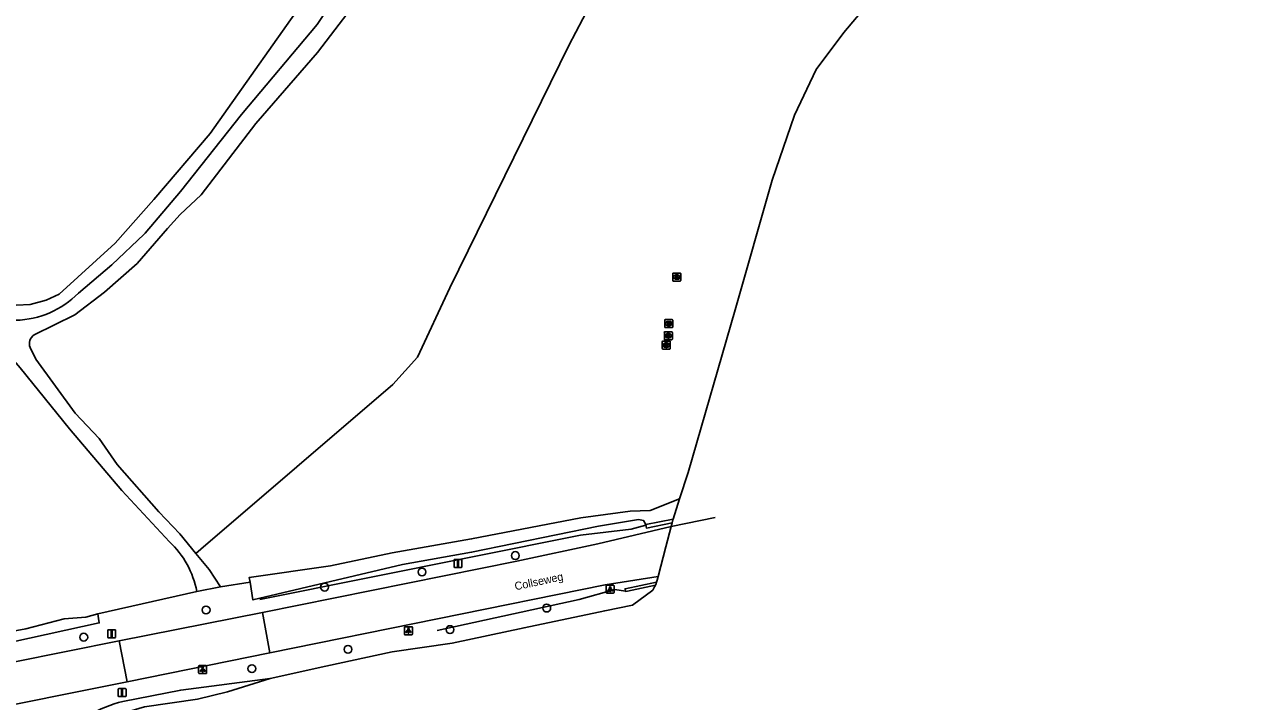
# Model space of a CAD drawing. Extents: x 164494 to 166241, y 382475 to 384494.
# Drawn here: x 165444.2 to 165598.1, y 384088.3 to 384172.8 of the extents above; entities that cross this region are included whole.
import ezdxf

# ---------------------------------------------------------------- set-up
doc = ezdxf.new("R2010")
doc.units = 0
for name, color, linetype in [('IMGEO_Afsluitpaal', 7, 'Continuous'), ('IMGEO_Boom', 7, 'Continuous'), ('IMGEO_Grasland_agrarisch', 7, 'Continuous'), ('IMGEO_Grasland_overig', 7, 'Continuous'), ('IMGEO_Groenvoorziening', 7, 'Continuous'), ('IMGEO_Hek', 7, 'Continuous'), ('IMGEO_Lichtpunt', 7, 'Continuous'), ('IMGEO_Loofbos', 7, 'Continuous'), ('IMGEO_Muur', 7, 'Continuous'), ('IMGEO_Openbare_ruimte_label', 7, 'Continuous'), ('IMGEO_Rijbaan_lokaal_gesloten', 7, 'Continuous'), ('IMGEO_Rioolput', 7, 'Continuous'), ('IMGEO_Rivier', 7, 'Continuous'), ('IMGEO_Verkeersbordpaal', 7, 'Continuous'), ('IMGEO_Waterloop', 7, 'Continuous')]:
    doc.layers.add(name, color=color, linetype=linetype)

msp = doc.modelspace()

# ---------------------------------------------------------------- linework, layer by layer
at = {"layer": 'IMGEO_Afsluitpaal'}
for p, q in [((165497.8, 384105.09), (165497.8, 384105.89)), ((165497.8, 384105.89), (165497.8, 384105.09)), ((165497.9, 384105.99), (165498.69, 384105.99)), ((165498.69, 384105.99), (165497.9, 384105.99)), ((165498.79, 384105.89), (165498.79, 384105.09)), ((165498.79, 384105.09), (165498.79, 384105.89)), ((165498.69, 384104.99), (165497.9, 384104.99)), ((165497.9, 384104.99), (165498.69, 384104.99))]:
    msp.add_line(p, q, dxfattribs=at)
msp.add_lwpolyline([(165498.22, 384105.86), (165498.37, 384105.86), (165498.37, 384105.11), (165498.22, 384105.11), (165498.22, 384105.86)], dxfattribs=at)
for centre, start, end in [((165497.9, 384105.89), 90, 180), ((165497.9, 384105.89), 90, 180), ((165498.69, 384105.89), 0, 90), ((165498.69, 384105.89), 360, 90), ((165497.9, 384105.09), 180, 270), ((165497.9, 384105.09), 180, 270), ((165498.69, 384105.09), 270, 0), ((165498.69, 384105.09), 270, 0)]:
    msp.add_arc(centre, 0.1, start, end, dxfattribs=at)
at = {"layer": 'IMGEO_Boom'}
for centre in [(165505.45, 384106.47), (165493.8, 384104.42), (165481.63, 384102.53), (165466.83, 384099.67), (165509.38, 384099.91), (165497.29, 384097.22), (165451.55, 384096.27), (165484.56, 384094.75), (165472.55, 384092.34)]:
    msp.add_circle(centre, 0.489, dxfattribs=at)
at = {"layer": 'IMGEO_Grasland_agrarisch'}
for points in [[(165465.57, 384106.74), (165466.17, 384107.26), (165490.15, 384127.83), (165493.22, 384131.25), (165497.28, 384139.93), (165512.14, 384170.22), (165523.5, 384191.93)], [(165472.35, 384103.15), (165468.64, 384102.58)]]:
    msp.add_lwpolyline(points, dxfattribs=at)
at = {"layer": 'IMGEO_Grasland_overig'}
msp.add_lwpolyline([(165439.58, 384138.15), (165443.14, 384137.77), (165444.87, 384137.84), (165446.85, 384138.39), (165448.47, 384139.12), (165455.48, 384145.52), (165460.29, 384150.96), (165467.36, 384159.23), (165480.29, 384177.58), (165497.03, 384199.38), (165497.99, 384201.63), (165497.95, 384203.22), (165497.56, 384205.09), (165477.73, 384217.77), (165475.07, 384217.77), (165472.61, 384217.34), (165461.02, 384205.38)], dxfattribs=at)
at = {"layer": 'IMGEO_Groenvoorziening'}
msp.add_lwpolyline([(165474.83, 384091.12), (165463.67, 384089.66), (165456.44, 384088.25)], dxfattribs=at)
msp.add_arc((165460.37, 384072.72), 16.02, 104.1806, 120.6638, dxfattribs=at)
at = {"layer": 'IMGEO_Hek'}
for points in [[(165473.56, 384100.97), (165513.59, 384109), (165519.92, 384109.76), (165521.77, 384110.26)], [(165519.2, 384102.04), (165517.9, 384102.24), (165513.44, 384100.99), (165495.71, 384097.09)]]:
    msp.add_lwpolyline(points, dxfattribs=at)
at = {"layer": 'IMGEO_Lichtpunt'}
for p, q in [((165516.81, 384102.66), (165516.81, 384101.86)), ((165516.81, 384102.66), (165516.81, 384101.86)), ((165517.71, 384102.76), (165516.9, 384102.76)), ((165517.71, 384102.76), (165516.9, 384102.76)), ((165517.81, 384101.86), (165517.81, 384102.66)), ((165517.81, 384101.86), (165517.81, 384102.66)), ((165516.9, 384101.76), (165517.71, 384101.76)), ((165516.9, 384101.76), (165517.71, 384101.76)), ((165491.61, 384097.48), (165491.61, 384096.67)), ((165491.61, 384097.48), (165491.61, 384096.67)), ((165492.51, 384097.57), (165491.7, 384097.57)), ((165492.51, 384097.57), (165491.7, 384097.57)), ((165491.7, 384096.58), (165492.51, 384096.58)), ((165491.7, 384096.58), (165492.51, 384096.58)), ((165492.6, 384096.67), (165492.6, 384097.48)), ((165492.6, 384096.67), (165492.6, 384097.48)), ((165465.9, 384092.63), (165465.9, 384091.82)), ((165465.9, 384092.63), (165465.9, 384091.82)), ((165466.8, 384092.72), (165466, 384092.72)), ((165466.8, 384092.72), (165466, 384092.72)), ((165466, 384091.72), (165466.8, 384091.72)), ((165466, 384091.72), (165466.8, 384091.72)), ((165466.9, 384091.82), (165466.9, 384092.63)), ((165466.9, 384091.82), (165466.9, 384092.63))]:
    msp.add_line(p, q, dxfattribs=at)
for points in [[(165517.18, 384102.33), (165517.22, 384102.3), (165517.04, 384102.04), (165517, 384102.07), (165517.18, 384102.33)], [(165517.29, 384102.28), (165517.33, 384102.28), (165517.33, 384101.96), (165517.29, 384101.96), (165517.29, 384102.28)], [(165517.4, 384102.3), (165517.43, 384102.33), (165517.62, 384102.06), (165517.58, 384102.04), (165517.4, 384102.3)], [(165491.98, 384097.14), (165492.02, 384097.12), (165491.83, 384096.85), (165491.79, 384096.88), (165491.98, 384097.14)], [(165492.08, 384097.1), (165492.13, 384097.1), (165492.13, 384096.77), (165492.08, 384096.77), (165492.08, 384097.1)], [(165492.19, 384097.12), (165492.23, 384097.14), (165492.42, 384096.88), (165492.38, 384096.85), (165492.19, 384097.12)], [(165466.28, 384092.29), (165466.31, 384092.26), (165466.13, 384092), (165466.09, 384092.03), (165466.28, 384092.29)], [(165466.38, 384092.24), (165466.43, 384092.24), (165466.43, 384091.92), (165466.38, 384091.92), (165466.38, 384092.24)], [(165466.49, 384092.26), (165466.53, 384092.29), (165466.71, 384092.03), (165466.67, 384092), (165466.49, 384092.26)]]:
    msp.add_lwpolyline(points, dxfattribs=at)
for centre in [(165517.31, 384102.46), (165492.11, 384097.28), (165466.4, 384092.42)]:
    msp.add_circle(centre, 0.0994, dxfattribs=at)
for centre, start, end in [((165516.9, 384102.66), 90, 180), ((165516.9, 384102.66), 90, 180), ((165517.71, 384102.66), 0, 90), ((165517.71, 384102.66), 0, 90), ((165516.9, 384101.86), 180, 270), ((165516.9, 384101.86), 180, 270), ((165517.71, 384101.86), 270, 0), ((165517.71, 384101.86), 270, 360), ((165491.7, 384097.48), 90, 180), ((165491.7, 384097.48), 90, 180), ((165491.7, 384096.67), 180, 270), ((165491.7, 384096.67), 180, 270), ((165492.51, 384097.48), 0, 90), ((165492.51, 384097.48), 0, 90), ((165492.51, 384096.67), 270, 0), ((165492.51, 384096.67), 270, 360), ((165466, 384092.63), 90, 180), ((165466, 384092.63), 90, 180), ((165466, 384091.82), 180, 270), ((165466, 384091.82), 180, 270), ((165466.8, 384092.63), 0, 90), ((165466.8, 384092.63), 0, 90), ((165466.8, 384091.82), 270, 0), ((165466.8, 384091.82), 270, 360)]:
    msp.add_arc(centre, 0.0946, start, end, dxfattribs=at)
at = {"layer": 'IMGEO_Loofbos'}
msp.add_lwpolyline([(165465.67, 384101.99), (165453.31, 384099.19)], dxfattribs=at)
at = {"layer": 'IMGEO_Muur'}
for points in [[(165525.16, 384111.03), (165521.76, 384110.34)], [(165521.76, 384110.34), (165521.83, 384109.91), (165525.04, 384110.58)], [(165525.16, 384111.03), (165525.12, 384110.92), (165525.04, 384110.58)], [(165523.09, 384103.15), (165519.16, 384102.33), (165519.21, 384101.98), (165519.48, 384102.03), (165522.4, 384102.66), (165522.97, 384102.78)], [(165523.09, 384103.15), (165523.02, 384102.86), (165522.97, 384102.78)]]:
    msp.add_lwpolyline(points, dxfattribs=at)
at = {"layer": 'IMGEO_Rijbaan_lokaal_gesloten'}
for points in [[(165524.91, 384110.11), (165515.76, 384107.92), (165505.63, 384105.79), (165473.88, 384099.35)], [(165524.91, 384110.11), (165524.25, 384107.57), (165523.28, 384103.86)], [(165530.43, 384111.24), (165524.91, 384110.11)], [(165474.8, 384094.32), (165516.68, 384102.82), (165523.28, 384103.86)], [(165455.96, 384095.8), (165473.88, 384099.35)], [(165473.88, 384099.35), (165474.8, 384094.32)], [(165411.91, 384087.02), (165416.2, 384087.82), (165455.96, 384095.8)], [(165456.98, 384090.71), (165455.96, 384095.8)], [(165474.8, 384094.32), (165456.98, 384090.71)], [(165456.98, 384090.71), (165416.61, 384082.6)]]:
    msp.add_lwpolyline(points, dxfattribs=at)
at = {"layer": 'IMGEO_Rioolput'}
for p, q in [((165525.12, 384140.84), (165525.12, 384141.7)), ((165525.19, 384141.77), (165526.05, 384141.77)), ((165526.05, 384140.77), (165525.19, 384140.77)), ((165525.63, 384140.99), (165525.6, 384140.99)), ((165525.61, 384141.55), (165525.63, 384141.55)), ((165526.12, 384141.7), (165526.12, 384140.84)), ((165524.12, 384135.03), (165524.12, 384135.88)), ((165524.2, 384135.96), (165525.05, 384135.96)), ((165525.05, 384134.96), (165524.2, 384134.96)), ((165524.61, 384135.74), (165524.63, 384135.74)), ((165524.63, 384135.18), (165524.61, 384135.18)), ((165525.12, 384135.88), (165525.12, 384135.03)), ((165523.81, 384132.34), (165523.81, 384133.19)), ((165523.89, 384133.27), (165524.74, 384133.27)), ((165524.07, 384133.51), (165524.07, 384134.36)), ((165524.14, 384134.43), (165525, 384134.43)), ((165525, 384133.43), (165524.14, 384133.43)), ((165524.3, 384133.05), (165524.33, 384133.05)), ((165524.58, 384133.65), (165524.55, 384133.65)), ((165524.56, 384134.21), (165524.58, 384134.21)), ((165524.81, 384133.19), (165524.81, 384132.34)), ((165525.07, 384134.36), (165525.07, 384133.51)), ((165524.74, 384132.27), (165523.89, 384132.27)), ((165524.32, 384132.49), (165524.3, 384132.49))]:
    msp.add_line(p, q, dxfattribs=at)
for points in [[(165525.12, 384140.84), (165525.12, 384141.7)], [(165525.19, 384141.77), (165526.05, 384141.77)], [(165526.05, 384140.77), (165525.19, 384140.77)], [(165525.71, 384141.47), (165525.46, 384141.47), (165525.46, 384141.07)], [(165525.46, 384141.07), (165525.58, 384141.07), (165525.58, 384141.23), (165525.59, 384141.23)], [(165525.63, 384141.39), (165525.58, 384141.39), (165525.58, 384141.31)], [(165525.58, 384141.31), (165525.63, 384141.31)], [(165525.64, 384141.2), (165525.71, 384141.07), (165525.85, 384141.07), (165525.78, 384141.2)], [(165526.12, 384141.7), (165526.12, 384140.84)], [(165524.12, 384135.03), (165524.12, 384135.88)], [(165524.2, 384135.96), (165525.05, 384135.96)], [(165525.05, 384134.96), (165524.2, 384134.96)], [(165524.71, 384135.65), (165524.46, 384135.66), (165524.46, 384135.26)], [(165524.46, 384135.26), (165524.58, 384135.26), (165524.58, 384135.42), (165524.59, 384135.42)], [(165524.64, 384135.58), (165524.58, 384135.58), (165524.58, 384135.49)], [(165524.58, 384135.49), (165524.63, 384135.49)], [(165524.64, 384135.39), (165524.71, 384135.26), (165524.85, 384135.26), (165524.79, 384135.38)], [(165525.12, 384135.88), (165525.12, 384135.03)], [(165523.81, 384132.34), (165523.81, 384133.19)], [(165523.89, 384133.27), (165524.74, 384133.27)], [(165524.07, 384133.51), (165524.07, 384134.36)], [(165524.14, 384134.43), (165525, 384134.43)], [(165525, 384133.43), (165524.14, 384133.43)], [(165524.66, 384134.13), (165524.4, 384134.13), (165524.4, 384133.73)], [(165524.4, 384133.73), (165524.53, 384133.73), (165524.53, 384133.9), (165524.54, 384133.9)], [(165524.58, 384134.05), (165524.53, 384134.05), (165524.53, 384133.97)], [(165524.53, 384133.97), (165524.58, 384133.97)], [(165524.59, 384133.87), (165524.66, 384133.73), (165524.8, 384133.73), (165524.73, 384133.86)], [(165524.81, 384133.19), (165524.81, 384132.34)], [(165525.07, 384134.36), (165525.07, 384133.51)], [(165524.74, 384132.27), (165523.89, 384132.27)], [(165524.4, 384132.96), (165524.15, 384132.97), (165524.15, 384132.57)], [(165524.15, 384132.57), (165524.27, 384132.57), (165524.27, 384132.73), (165524.28, 384132.73)], [(165524.33, 384132.89), (165524.27, 384132.89), (165524.27, 384132.8)], [(165524.27, 384132.8), (165524.32, 384132.8)], [(165524.33, 384132.7), (165524.4, 384132.57), (165524.54, 384132.57), (165524.48, 384132.69)]]:
    msp.add_lwpolyline(points, dxfattribs=at)
for centre, radius, start, end in [((165525.2, 384141.7), 0.0765, 91.552, 178.448), ((165525.2, 384141.7), 0.0765, 91.552, 178.448), ((165525.2, 384140.85), 0.0765, 181.552, 268.448), ((165525.2, 384140.85), 0.0765, 181.552, 268.448), ((165525.59, 384141.18), 0.0533, 26.0293, 88.6989), ((165525.64, 384141.29), 0.0964, 77.0061, 93.1865), ((165525.62, 384141.5), 0.19, 274.7715, 282.9687), ((165525.65, 384141.35), 0.0378, 276.6634, 79.6772), ((165525.71, 384141.36), 0.109, 350.3612, 89.416), ((165525.71, 384141.36), 0.112, 277.5842, 350.9817), ((165525.69, 384141.14), 0.108, 29.5134, 73.7905), ((165526.04, 384141.7), 0.0765, 1.552, 88.448), ((165526.04, 384141.7), 0.0765, 1.552, 88.448), ((165526.04, 384140.85), 0.0765, 271.552, 358.448), ((165526.04, 384140.85), 0.0765, 271.552, 358.448), ((165524.2, 384135.88), 0.0765, 91.552, 178.448), ((165524.2, 384135.88), 0.0765, 91.552, 178.448), ((165524.2, 384135.03), 0.0765, 181.552, 268.448), ((165524.2, 384135.03), 0.0765, 181.552, 268.448), ((165524.59, 384135.37), 0.0533, 26.0293, 88.6989), ((165524.62, 384135.68), 0.19, 274.7715, 282.9687), ((165524.64, 384135.48), 0.0964, 77.0061, 93.1865), ((165524.66, 384135.54), 0.0378, 276.6634, 79.6772), ((165524.71, 384135.55), 0.109, 350.3612, 89.416), ((165524.71, 384135.54), 0.112, 277.5842, 350.9817), ((165524.69, 384135.33), 0.108, 29.5134, 73.7905), ((165525.05, 384135.88), 0.0765, 1.552, 88.448), ((165525.05, 384135.88), 0.0765, 1.552, 88.448), ((165525.05, 384135.03), 0.0765, 271.552, 358.448), ((165525.05, 384135.03), 0.0765, 271.552, 358.448), ((165523.89, 384133.19), 0.0765, 91.552, 178.448), ((165523.89, 384133.19), 0.0765, 91.552, 178.448), ((165524.14, 384134.36), 0.0765, 91.552, 178.448), ((165524.14, 384134.36), 0.0765, 91.552, 178.448), ((165524.14, 384133.51), 0.0765, 181.552, 268.448), ((165524.14, 384133.51), 0.0765, 181.552, 268.448), ((165524.54, 384133.84), 0.0533, 26.0293, 88.6989), ((165524.59, 384133.96), 0.0964, 77.0061, 93.1865), ((165524.57, 384134.16), 0.19, 274.7715, 282.9687), ((165524.6, 384134.01), 0.0378, 276.6634, 79.6772), ((165524.66, 384134.02), 0.109, 350.3612, 89.416), ((165524.65, 384134.02), 0.112, 277.5842, 350.9817), ((165524.64, 384133.81), 0.108, 29.5134, 73.7905), ((165524.74, 384133.19), 0.0765, 1.552, 88.448), ((165524.74, 384133.19), 0.0765, 1.552, 88.448), ((165524.99, 384134.36), 0.0765, 1.552, 88.448), ((165524.99, 384134.36), 0.0765, 1.552, 88.448), ((165524.99, 384133.51), 0.0765, 271.552, 358.448), ((165524.99, 384133.51), 0.0765, 271.552, 358.448), ((165523.89, 384132.34), 0.0765, 181.552, 268.448), ((165523.89, 384132.34), 0.0765, 181.552, 268.448), ((165524.28, 384132.68), 0.0533, 26.0293, 88.6989), ((165524.31, 384132.99), 0.19, 274.7715, 282.9687), ((165524.33, 384132.79), 0.0964, 77.0061, 93.1865), ((165524.35, 384132.85), 0.0378, 276.6634, 79.6772), ((165524.4, 384132.85), 0.109, 350.3612, 89.416), ((165524.4, 384132.85), 0.112, 277.5842, 350.9817), ((165524.38, 384132.64), 0.108, 29.5134, 73.7905), ((165524.74, 384132.34), 0.0765, 271.552, 358.448), ((165524.74, 384132.34), 0.0765, 271.552, 358.448)]:
    msp.add_arc(centre, radius, start, end, dxfattribs=at)
for centre, major_axis, ratio, start_param, end_param in [((165525.61, 384141.27), (-0.387, 0.002), 0.722429, 4.712389, 7.853982), ((165525.63, 384141.27), (-0.39, 0.002), 0.717154, 1.570796, 4.712389), ((165524.61, 384135.46), (-0.387, 0.002), 0.722429, 4.712389, 7.853982), ((165524.63, 384135.46), (-0.39, 0.002), 0.717154, 1.570796, 4.712389), ((165524.3, 384132.77), (-0.387, 0.002), 0.722429, 4.712389, 7.853982), ((165524.56, 384133.93), (-0.387, 0.002), 0.722429, 4.712389, 7.853982), ((165524.32, 384132.77), (-0.39, 0.002), 0.717154, 1.570796, 4.712389), ((165524.58, 384133.93), (-0.39, 0.002), 0.717154, 1.570796, 4.712389)]:
    msp.add_ellipse(centre, major_axis=major_axis, ratio=ratio, start_param=start_param, end_param=end_param, dxfattribs=at)
at = {"layer": 'IMGEO_Rivier'}
for points in [[(165598.14, 384295.04), (165590.06, 384287.65), (165583.02, 384280.57), (165580.29, 384277.53), (165578.81, 384274.57), (165577.42, 384269.36), (165576.64, 384264.49), (165576.33, 384257.32), (165576.07, 384247.02), (165575.68, 384237.33), (165575.29, 384231.86), (165574.16, 384225.73), (165572.34, 384219.08), (165567.12, 384207), (165558.22, 384188.14), (165555.48, 384182.75), (165552.57, 384179.1), (165546.49, 384171.84), (165543.02, 384167.19), (165540.32, 384161.5), (165537.54, 384153.38), (165532.9, 384137.17), (165527.03, 384116.87), (165525.96, 384113.54)], [(165525.96, 384113.54), (165525.16, 384111.03)], [(165525.04, 384110.58), (165524.91, 384110.11)], [(165523.28, 384103.86), (165523.16, 384103.39), (165523.09, 384103.15)], [(165522.97, 384102.78), (165522.85, 384102.57), (165522.62, 384102.16), (165520.08, 384100.26), (165516.62, 384099.57), (165506.54, 384097.44), (165497.56, 384095.53), (165490.08, 384094.46), (165481.78, 384092.64), (165474.83, 384091.12)], [(165474.83, 384091.12), (165469.52, 384089.43), (165465.75, 384088.54), (165459.14, 384087.57), (165454.07, 384086.05), (165453.57, 384085.73), (165453.13, 384084.89), (165451.41, 384078.33), (165450.57, 384072.76), (165450.89, 384063.84), (165450.66, 384063.34), (165449.28, 384062.17), (165448.74, 384061.82)]]:
    msp.add_lwpolyline(points, dxfattribs=at)
at = {"layer": 'IMGEO_Verkeersbordpaal'}
for p, q in [((165454.54, 384096.3), (165454.54, 384097.1)), ((165454.54, 384097.1), (165454.54, 384096.3)), ((165454.64, 384097.2), (165455.43, 384097.2)), ((165455.43, 384097.2), (165454.64, 384097.2)), ((165455.43, 384096.2), (165454.64, 384096.2)), ((165454.64, 384096.2), (165455.43, 384096.2)), ((165455.53, 384097.1), (165455.53, 384096.3)), ((165455.53, 384096.3), (165455.53, 384097.1)), ((165455.84, 384088.95), (165455.84, 384089.75)), ((165455.84, 384089.75), (165455.84, 384088.95)), ((165455.94, 384089.85), (165456.73, 384089.85)), ((165456.73, 384089.85), (165455.94, 384089.85)), ((165456.73, 384088.85), (165455.94, 384088.85)), ((165455.94, 384088.85), (165456.73, 384088.85)), ((165456.83, 384089.75), (165456.83, 384088.95)), ((165456.83, 384088.95), (165456.83, 384089.75))]:
    msp.add_line(p, q, dxfattribs=at)
for points in [[(165454.96, 384097.07), (165455.11, 384097.07), (165455.11, 384096.32), (165454.96, 384096.32), (165454.96, 384097.07)], [(165456.26, 384089.72), (165456.41, 384089.72), (165456.41, 384088.97), (165456.26, 384088.97), (165456.26, 384089.72)]]:
    msp.add_lwpolyline(points, dxfattribs=at)
for centre, start, end in [((165454.64, 384097.1), 90, 180), ((165454.64, 384097.1), 90, 180), ((165454.64, 384096.3), 180, 270), ((165454.64, 384096.3), 180, 270), ((165455.43, 384097.1), 0, 90), ((165455.43, 384097.1), 360, 90), ((165455.43, 384096.3), 270, 0), ((165455.43, 384096.3), 270, 0), ((165455.94, 384089.75), 90, 180), ((165455.94, 384089.75), 90, 180), ((165455.94, 384088.95), 180, 270), ((165455.94, 384088.95), 180, 270), ((165456.73, 384089.75), 0, 90), ((165456.73, 384089.75), 360, 90), ((165456.73, 384088.95), 270, 0), ((165456.73, 384088.95), 270, 0)]:
    msp.add_arc(centre, 0.1, start, end, dxfattribs=at)
at = {"layer": 'IMGEO_Waterloop'}
for points in [[(165461.02, 384205.38), (165472.44, 384220.82), (165473.53, 384221.53), (165474.62, 384221.45), (165477.82, 384220.15), (165500, 384206.23), (165502.2, 384204.85), (165502.73, 384203.53), (165502.12, 384202.18), (165500, 384199.83), (165495.84, 384195.21), (165490.34, 384186.79), (165485.08, 384179.41), (165480.7, 384172.82), (165471.24, 384161.59), (165463.63, 384151.96), (165459.21, 384146.75), (165459.08, 384146.62), (165455.04, 384142.8), (165450.89, 384139.25)], [(165445.37, 384134.05), (165450.45, 384136.57), (165454.15, 384139.37), (165458.22, 384142.96), (165462.03, 384147.32), (165463.59, 384149.1), (165466.23, 384151.54), (165473.04, 384160.47), (165480.74, 384169.34), (165487.13, 384177.71), (165489.01, 384180.95), (165490.57, 384184.66), (165495.63, 384191.5), (165500, 384197.07), (165503.16, 384201.09), (165504.83, 384202.25), (165506.56, 384203.21)], [(165396.43, 384098.96), (165393.36, 384102.54), (165376.05, 384120.38), (165371.06, 384125.95), (165369.98, 384127.15), (165369.19, 384128.51), (165368.79, 384129.53), (165371.85, 384132.31), (165379.84, 384138.36), (165397.44, 384150.98), (165410.63, 384160.2), (165419.9, 384165.79), (165426.11, 384155.98), (165431.82, 384145.09), (165434.69, 384140.9), (165436.54, 384138.19), (165443.62, 384129.92), (165449.75, 384122.32), (165456.3, 384114.59), (165462.24, 384108.19)], [(165465.57, 384106.74), (165463.55, 384109.2), (165460.93, 384111.94), (165455.72, 384117.85), (165453.46, 384121.09), (165450.47, 384124.25), (165445.57, 384131.03), (165444.86, 384132.45)], [(165525.96, 384113.54), (165522.28, 384112.1), (165519.8, 384112), (165513.65, 384111.18), (165500, 384108.56), (165490.09, 384106.83), (165482.38, 384105.19), (165472.22, 384103.73), (165472.35, 384103.15)], [(165472.35, 384103.15), (165472.67, 384100.92), (165491.38, 384105.36), (165500, 384106.89), (165515.86, 384110.15), (165520.85, 384110.97), (165521.47, 384110.85), (165521.76, 384110.34)], [(165468.64, 384102.58), (165467.22, 384104.73), (165465.57, 384106.74)], [(165465.67, 384101.99), (165468.64, 384102.58)], [(165399.6, 384095.65), (165399.26, 384095.79), (165398.85, 384095.68), (165398.68, 384095.37), (165398.31, 384094.68), (165399, 384093.66), (165402.44, 384090.75), (165403.83, 384089.96), (165405.25, 384089.15), (165406.97, 384088.92), (165410.95, 384088.97), (165417.21, 384090.03), (165437.75, 384094.84), (165442.7, 384095.67), (165453.48, 384098.05), (165453.39, 384098.62), (165453.31, 384099.19)], [(165453.31, 384099.19), (165451.79, 384098.76), (165449.11, 384098.58), (165444.31, 384097.31), (165437.2, 384096.02), (165421.73, 384092.69), (165419.92, 384091.99), (165415.95, 384091.04), (165409.72, 384089.8), (165407.08, 384089.7), (165406.54, 384089.8), (165404.14, 384090.9), (165402.2, 384092.61), (165400.76, 384094.14), (165399.6, 384095.65)]]:
    msp.add_lwpolyline(points, dxfattribs=at)
for centre, radius, start, end in [((165442.77, 384147.31), 11.44, 271.5337, 315.1976), ((165446.03, 384132.96), 1.27, 121.1315, 203.701), ((165454.58, 384099.91), 11.28, 10.6315, 47.2169)]:
    msp.add_arc(centre, radius, start, end, dxfattribs=at)

# ---------------------------------------------------------------- texts
at = {"layer": 'IMGEO_Openbare_ruimte_label'}
msp.add_text('Collseweg', height=1, rotation=12.0067, dxfattribs=at).set_placement((165505.48, 384102.12))

doc.saveas('drawing.dxf')
